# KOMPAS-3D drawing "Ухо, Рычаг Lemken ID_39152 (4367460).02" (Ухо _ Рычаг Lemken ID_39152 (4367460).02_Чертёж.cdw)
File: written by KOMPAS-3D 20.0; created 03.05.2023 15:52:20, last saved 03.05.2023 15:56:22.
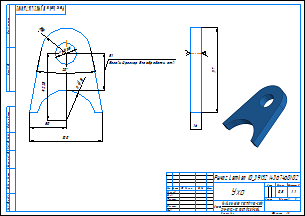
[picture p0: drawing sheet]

Sheet 1: A3, landscape

Document properties: Автор: factory; Масса: 0.803282

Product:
- Part/product: Ухо  | designation Рычаг Lemken ID_39152 (4367460).02
    Материал: Лист$d16х1400х6000 ГОСТ 19903-2015;295-09Г2-ГС ГОСТ 19281-2014$ (density 7850 kg/m3)
    Масса: 0.803282
    source file: Ухо _ Рычаг Lemken ID_39152 (4367460).02_Чертёж.cdw

Title block, sheet 1: Наименование: Ухо; designation: Рычаг Lemken ID_39152 (4367460).02; Материал: Лист 16х1400х6000 ГОСТ 19903-2015 295-09Г2-ГС ГОСТ 19281-2014; Масса: 0,8; Количество листов документа: 1; Форматы листов документа: A3; stored path: C:\Users\factory\Desktop\Чертежи\Рычаг Lemken ID_39152 (4367460)\Ухо _ Рычаг Lemken ID_39152 (4367460).02_Чертёж.cdw

Views: Вид 1, Спереди, Проекционный вид 2
Referenced files in C:\Users\factory\Desktop\Чертежи\Рычаг Lemken ID_39152 (4367460)\: Ухо _ Рычаг Lemken ID_39152 (4367460).02.m3d, Ухо _ Рычаг Lemken ID_39152 (4367460).02_Рис.jpg
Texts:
  Базовый размер для обработки отв.
  Ухо _ Рычаг Lemken ID_39152 (4367460).02_Рис.jpg
  Рычаг Lemken ID_39152 (4367460).02 Ухо
Dimensions and other numbers on the sheet: 100; 30,05; 35; 41,25; 92,25; 51; 50; 16; 117; 1:1; 1; 0,8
